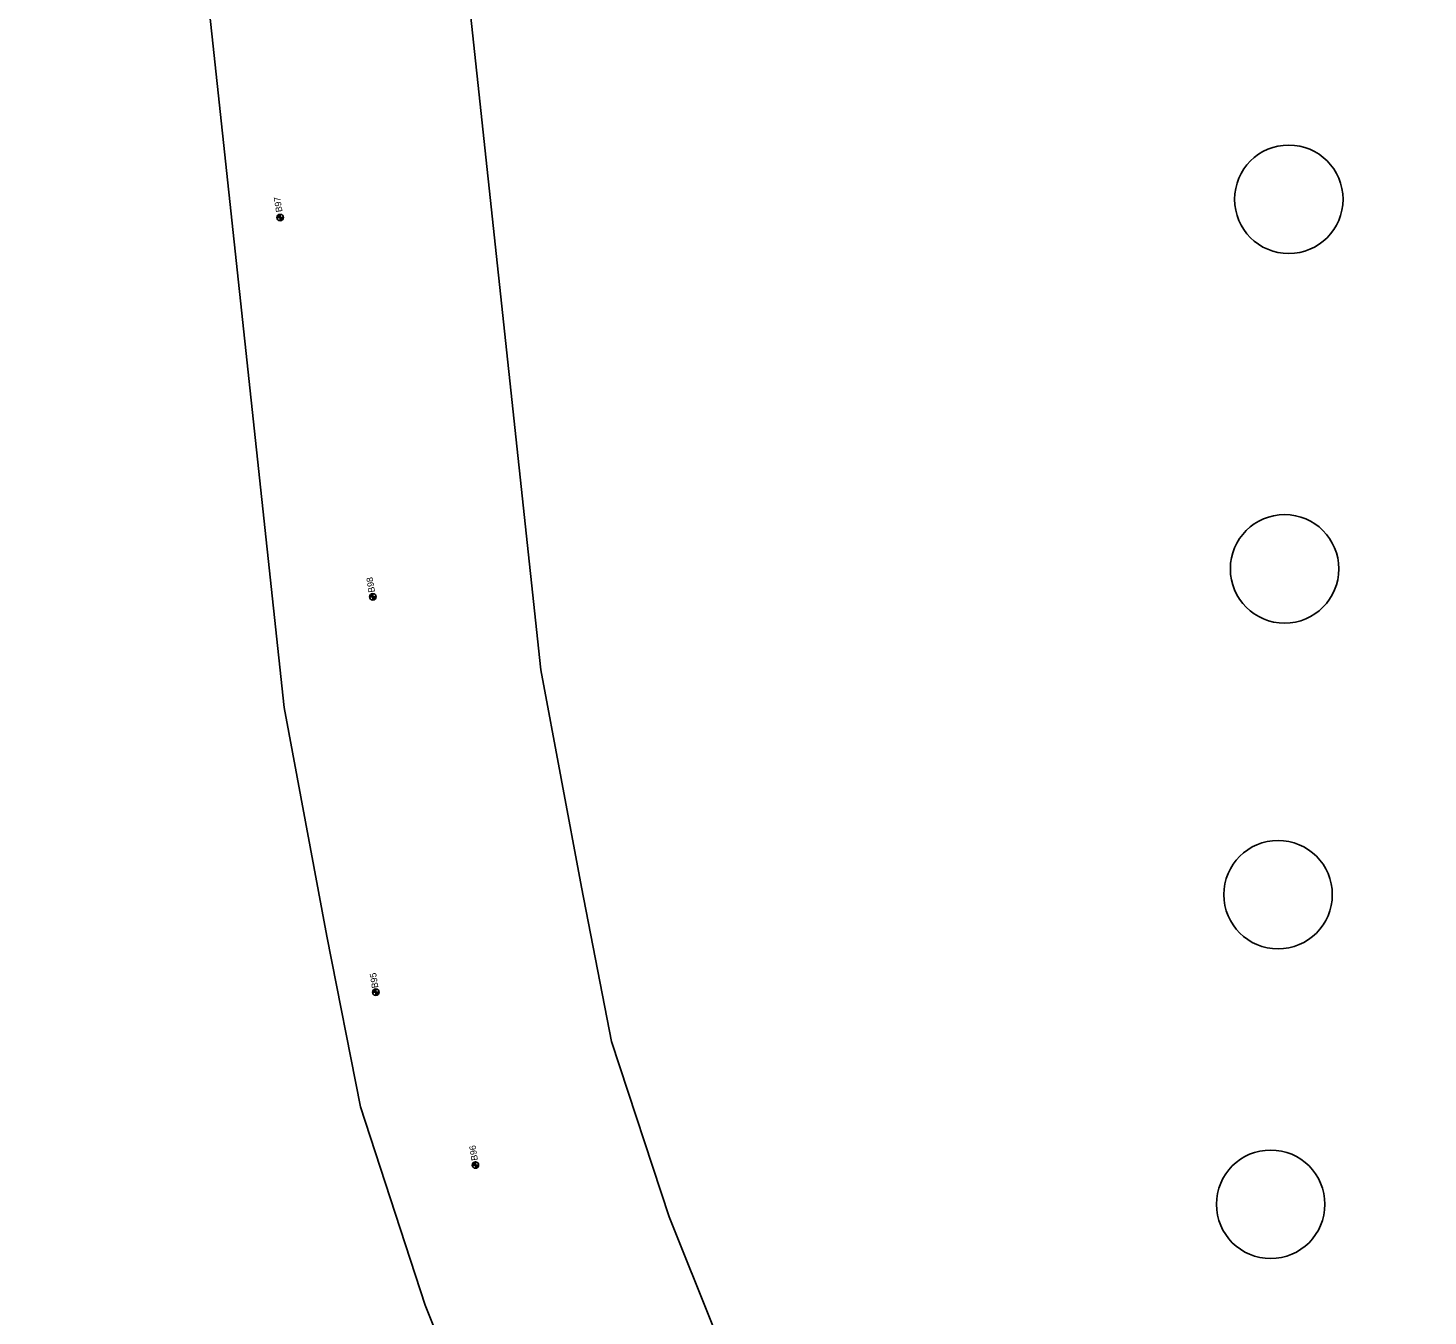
# Model space of a CAD drawing. Extents: x 327762 to 372792, y 127949 to 259367.
# Drawn here: x 355613 to 357773, y 180127 to 182113 of the extents above; entities that cross this region are included whole.
import ezdxf

# ---------------------------------------------------------------- set-up
doc = ezdxf.new("R2010")
doc.units = 0
for name, color, linetype in [('CE-TOPO-CONC-SLAB', 7, 'Continuous'), ('E_SOIL_BORE1 [KAPUR_CADDS_LEVELS]', 7, 'Continuous'), ('E_SOIL_BORE2 [KAPUR_CADDS_LEVELS]', 7, 'Continuous'), ('P_MARK', 7, 'Continuous'), ('P_TC', 7, 'Continuous')]:
    doc.layers.add(name, color=color, linetype=linetype)

msp = doc.modelspace()

# ---------------------------------------------------------------- linework, layer by layer
at = {"layer": 'CE-TOPO-CONC-SLAB'}
for centre in [(357558.5, 181849.2), (357552, 181279.1), (357541.9, 180776.5), (357530.5, 180298.8)]:
    msp.add_circle(centre, 83.7, dxfattribs=at)
at = {"layer": 'P_MARK'}
for p, q in [((355997.1, 181821), (356007.1, 181821)), ((356002.1, 181826), (356002.1, 181816)), ((356140, 181236), (356150, 181236)), ((356145, 181241), (356145, 181231)), ((356149.6, 180631), (356149.6, 180621)), ((356144.6, 180626), (356154.6, 180626)), ((356298.3, 180359.4), (356308.3, 180359.4)), ((356303.3, 180364.4), (356303.3, 180354.4))]:
    msp.add_line(p, q, dxfattribs=at)
for centre in [(356002.1, 181821), (356145, 181236), (356149.6, 180626), (356303.3, 180359.4)]:
    msp.add_circle(centre, 5, dxfattribs=at)
for centre, radius, start, end in [((356002.1, 181821), 4.5, 89.9869, 179.9869), ((356002.1, 181821), 4, 89.9869, 179.9869), ((356002.1, 181821), 3.5, 89.9869, 179.9869), ((356002.1, 181821), 3, 89.9869, 179.9869), ((356002.1, 181821), 2.5, 89.9869, 179.9869), ((356002.1, 181821), 2, 89.9869, 179.9869), ((356002.1, 181821), 1.5, 89.9869, 179.9869), ((356002.1, 181821), 1, 89.9869, 179.9869), ((356002.1, 181821), 0.5, 89.9869, 179.9869), ((356002.1, 181821), 4.5, 269.9869, 359.9869), ((356002.1, 181821), 4, 269.9869, 359.9869), ((356002.1, 181821), 3.5, 269.9869, 359.9869), ((356002.1, 181821), 3, 269.9869, 359.9869), ((356002.1, 181821), 2.5, 269.9869, 359.9869), ((356002.1, 181821), 2, 269.9869, 359.9869), ((356002.1, 181821), 1.5, 269.9869, 359.9869), ((356002.1, 181821), 1, 269.9869, 359.9869), ((356002.1, 181821), 0.5, 269.9869, 359.9869), ((356145, 181236), 4.5, 89.9869, 179.9869), ((356145, 181236), 4, 89.9869, 179.9869), ((356145, 181236), 3.5, 89.9869, 179.9869), ((356145, 181236), 3, 89.9869, 179.9869), ((356145, 181236), 2.5, 89.9869, 179.9869), ((356145, 181236), 2, 89.9869, 179.9869), ((356145, 181236), 1.5, 89.9869, 179.9869), ((356145, 181236), 1, 89.9869, 179.9869), ((356145, 181236), 0.5, 89.9869, 179.9869), ((356145, 181236), 4.5, 269.9869, 359.9869), ((356145, 181236), 4, 269.9869, 359.9869), ((356145, 181236), 3.5, 269.9869, 359.9869), ((356145, 181236), 3, 269.9869, 359.9869), ((356145, 181236), 2.5, 269.9869, 359.9869), ((356145, 181236), 2, 269.9869, 359.9869), ((356145, 181236), 1.5, 269.9869, 359.9869), ((356145, 181236), 1, 269.9869, 359.9869), ((356145, 181236), 0.5, 269.9869, 359.9869), ((356149.6, 180626), 4.5, 89.9869, 179.9869), ((356149.6, 180626), 4, 89.9869, 179.9869), ((356149.6, 180626), 3.5, 89.9869, 179.9869), ((356149.6, 180626), 3, 89.9869, 179.9869), ((356149.6, 180626), 2.5, 89.9869, 179.9869), ((356149.6, 180626), 2, 89.9869, 179.9869), ((356149.6, 180626), 1.5, 89.9869, 179.9869), ((356149.6, 180626), 1, 89.9869, 179.9869), ((356149.6, 180626), 0.5, 89.9869, 179.9869), ((356149.6, 180626), 4.5, 269.9869, 359.9869), ((356149.6, 180626), 4, 269.9869, 359.9869), ((356149.6, 180626), 3.5, 269.9869, 359.9869), ((356149.6, 180626), 3, 269.9869, 359.9869), ((356149.6, 180626), 2.5, 269.9869, 359.9869), ((356149.6, 180626), 2, 269.9869, 359.9869), ((356149.6, 180626), 1.5, 269.9869, 359.9869), ((356149.6, 180626), 1, 269.9869, 359.9869), ((356149.6, 180626), 0.5, 269.9869, 359.9869), ((356303.3, 180359.4), 4.5, 89.9869, 179.9869), ((356303.3, 180359.4), 4, 89.9869, 179.9869), ((356303.3, 180359.4), 3.5, 89.9869, 179.9869), ((356303.3, 180359.4), 3, 89.9869, 179.9869), ((356303.3, 180359.4), 2.5, 89.9869, 179.9869), ((356303.3, 180359.4), 2, 89.9869, 179.9869), ((356303.3, 180359.4), 1.5, 89.9869, 179.9869), ((356303.3, 180359.4), 1, 89.9869, 179.9869), ((356303.3, 180359.4), 0.5, 89.9869, 179.9869), ((356303.3, 180359.4), 4.5, 269.9869, 359.9869), ((356303.3, 180359.4), 4, 269.9869, 359.9869), ((356303.3, 180359.4), 3.5, 269.9869, 359.9869), ((356303.3, 180359.4), 3, 269.9869, 359.9869), ((356303.3, 180359.4), 2.5, 269.9869, 359.9869), ((356303.3, 180359.4), 2, 269.9869, 359.9869), ((356303.3, 180359.4), 1.5, 269.9869, 359.9869), ((356303.3, 180359.4), 1, 269.9869, 359.9869), ((356303.3, 180359.4), 0.5, 269.9869, 359.9869)]:
    msp.add_arc(centre, radius, start, end, dxfattribs=at)
at = {"layer": 'P_TC'}
for points in [[(356010.7, 184791.4), (356404.2, 181123.3), (356466.9, 180787.9), (356513.6, 180550.2), (356602.1, 180279.7), (356741, 179932.9), (356921, 179635), (357119.9, 179365.3), (357302.9, 179137.3), (357638, 178834.1), (357970.9, 178543), (358585.9, 178064.8), (358972.8, 177765.7), (359287.4, 177446.4), (359568.2, 177108.6), (359781.6, 176804.9), (359973.6, 176484.4), (360151.9, 176070.5), (360266.6, 175727.9), (360318.3, 175542.9)], [(359933.1, 175435.2), (359884.1, 175610.5), (359777.9, 175927.7), (359616.8, 176301.7), (359446, 176586.9), (359250.3, 176865.3), (358990.6, 177177.7), (358706.9, 177465.7), (358340.8, 177748.6), (357716.2, 178234.3), (357372.1, 178535.2), (357010.9, 178862.1), (356802.9, 179121.3), (356588.2, 179412.3), (356381.8, 179753.9), (356226, 180143), (356125.8, 180449.1), (356074, 180712.7), (356008.1, 181065.2), (355612.9, 184748.7)]]:
    msp.add_lwpolyline(points, dxfattribs=at)

# ---------------------------------------------------------------- texts
at = {"layer": 'E_SOIL_BORE1 [KAPUR_CADDS_LEVELS]'}
for s, p in [('B97', (356005.7, 181830.2)), ('B98', (356148.5, 181243.4)), ('B95', (356153.7, 180633.1))]:
    msp.add_text(s, height=10, rotation=98.957, dxfattribs=at).set_placement(p)
at = {"layer": 'E_SOIL_BORE2 [KAPUR_CADDS_LEVELS]'}
msp.add_text('B96', height=10, rotation=98.957, dxfattribs=at).set_placement((356307.2, 180367))

doc.saveas('drawing.dxf')
